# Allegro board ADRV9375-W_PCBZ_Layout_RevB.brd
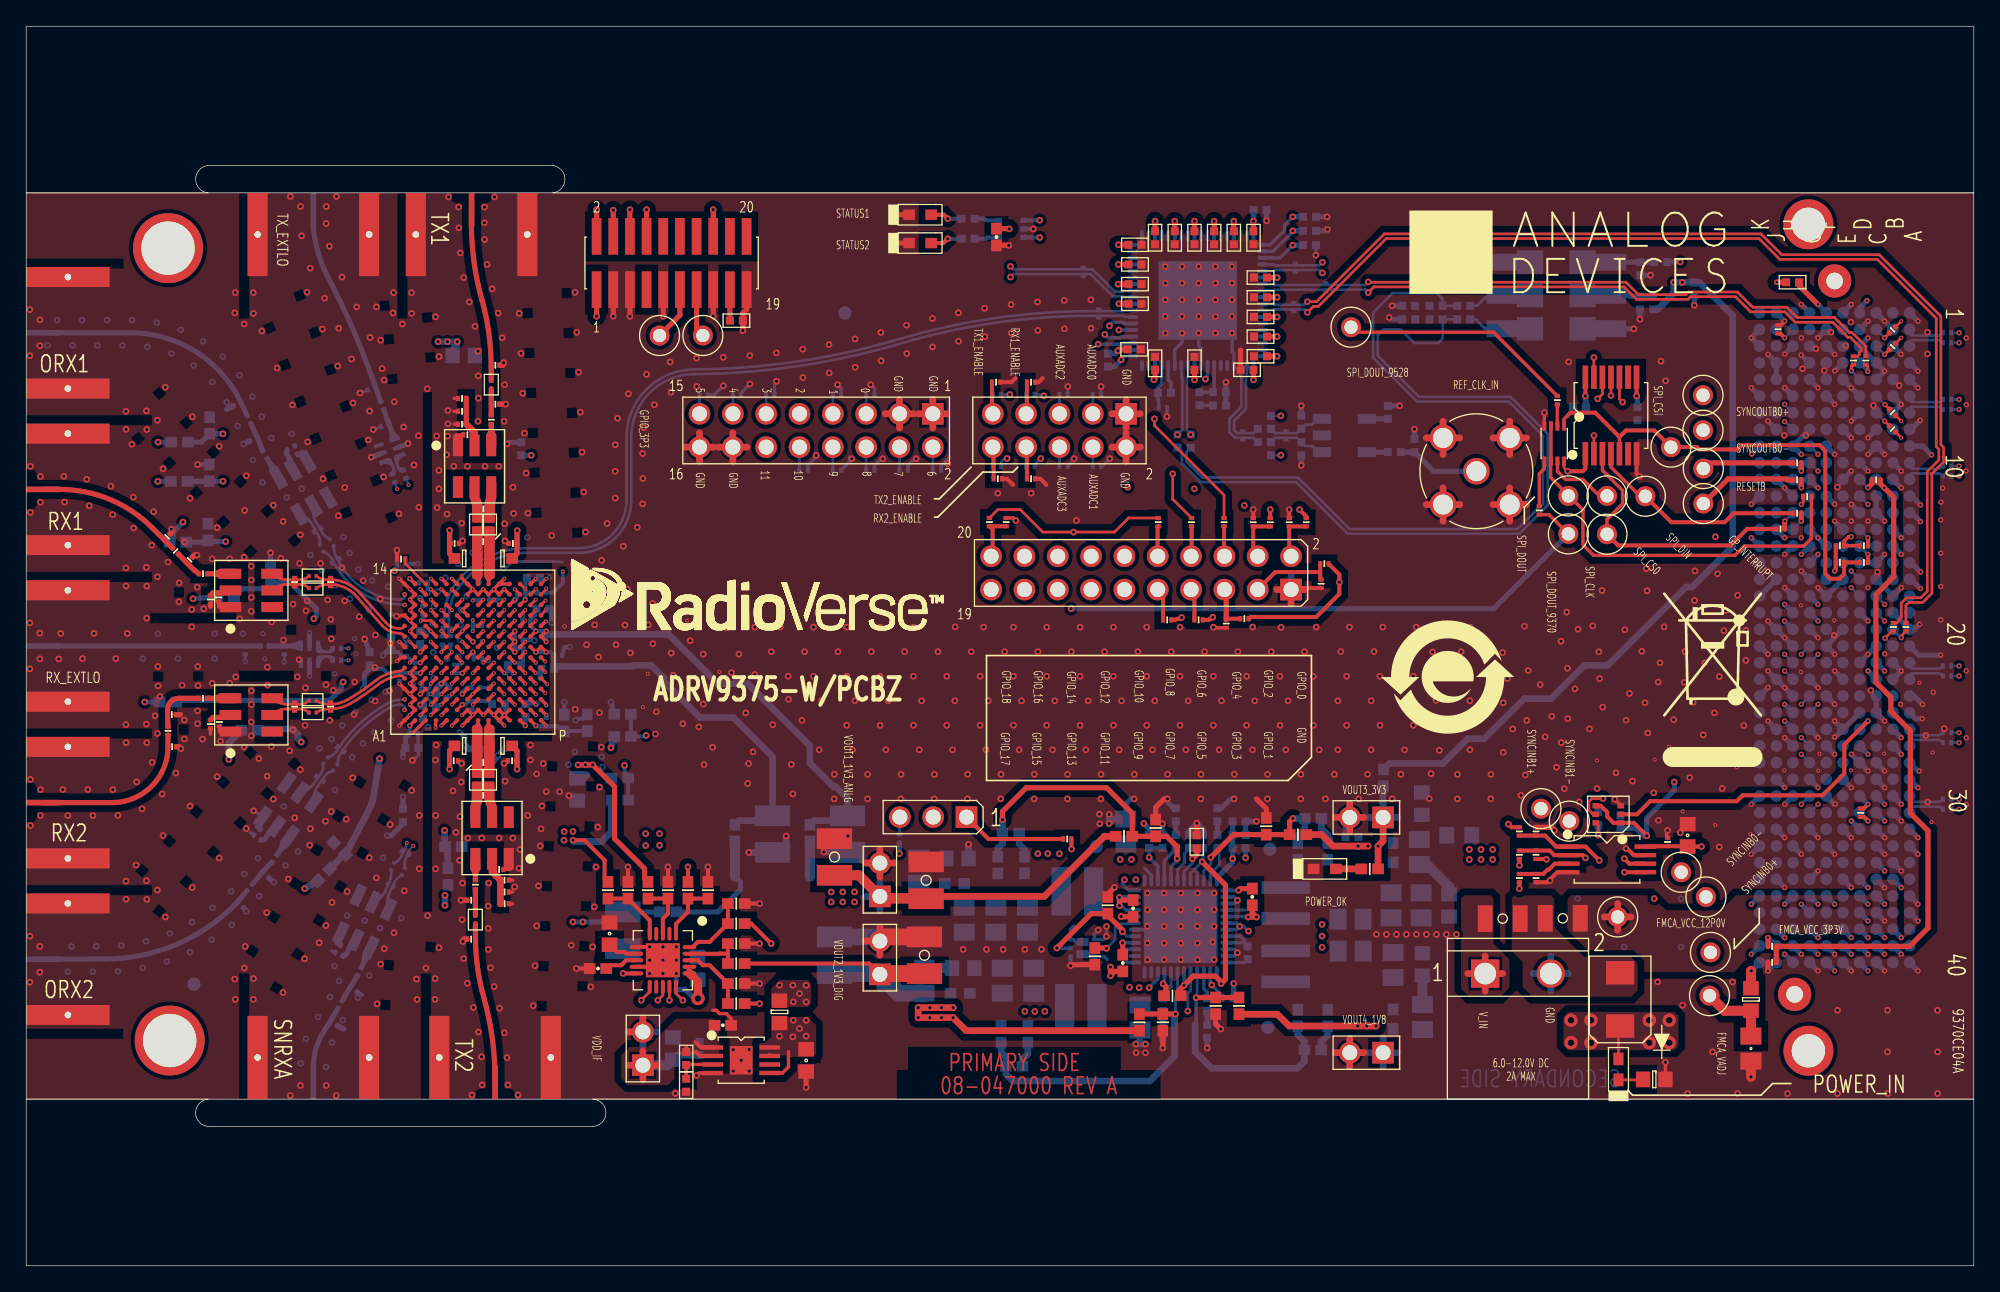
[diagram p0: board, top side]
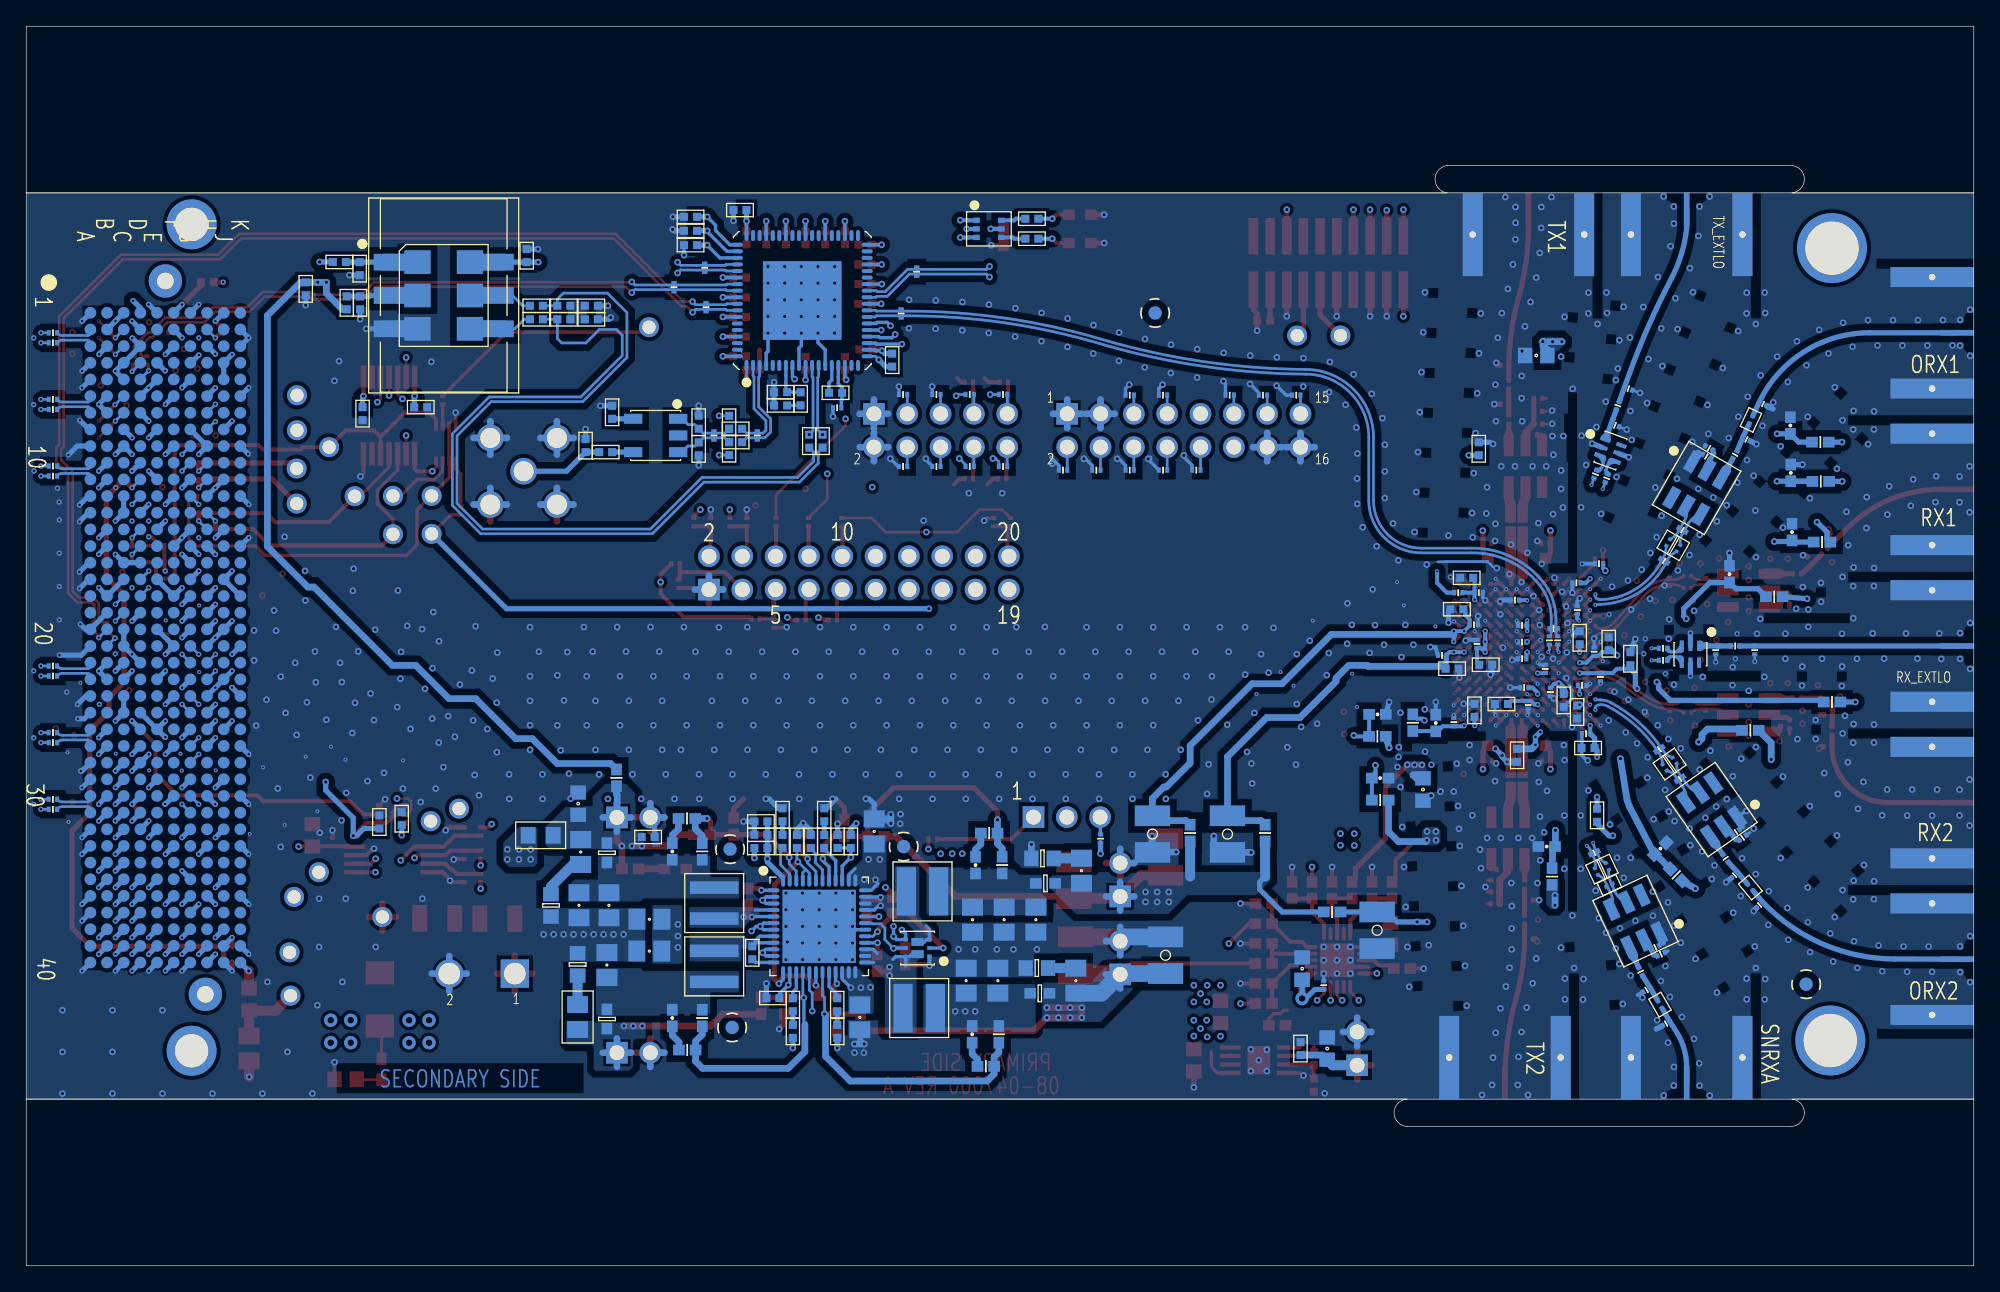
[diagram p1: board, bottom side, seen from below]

Outline 148.44 x 94.49 mm; copper layers: TOP, L2_GND, L3_PWR, L4_GND, L5_SIG, L6_GND, L7_SIG, L8_SIG, L9_GND, L10_SIG, L11_GND, L12_PWR, L13_GND, BOTTOM. Coordinates in mm from the lower left corner of the outline.
Outline path: 0,81.79 0,94.49 148.44,94.49 148.44,81.79 ; 0,81.79 0,12.7 ; 0,81.79 13.85,81.79 arc(12.91,82.83) 13.85,83.87 40.14,83.87 arc(41.06,82.83) 40.14,81.79 148.44,81.79 ; 0,81.79 148.44,81.79 ; 0,12.7 0,0 148.44,0 148.44,12.7 ; 0,12.7 148.44,12.7 ; 0,12.7 13.85,12.7 arc(12.91,11.66) 13.85,10.62 43.19,10.62 arc(44.19,11.66) 43.19,12.7 148.44,12.7 ; 148.44,12.7 148.44,81.79

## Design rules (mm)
net group DIFFPAIR0: nets SERDOUT0+ SERDOUT0-
net group DIFFPAIR1: nets SERDOUT1+ SERDOUT1-
net group DIFFPAIR2: nets SERDOUT3+ SERDOUT3-
net group DIFFPAIR3: nets SERDIN3+ SERDIN3-
net group DIFFPAIR4: nets SERDIN0+ SERDIN0-
net group DIFFPAIR5: nets SERDIN2+ SERDIN2-
net group DIFFPAIR13: nets SERDOUT2+ SERDOUT2-
net group DIFFPAIR15: nets SERDIN1+ SERDIN1-
net group DIFFPAIR16: nets TX_EXTLO+ TX_EXTLO-
net group DIFFPAIR17: nets ORX1+ ORX1-
net group DIFFPAIR18: nets RX1+ RX1-
net group DIFFPAIR19: nets RX2+ RX2-
net group DIFFPAIR20: nets ORX2+ ORX2-
net group DIFFPAIR22: nets RX_EXTLO+ RX_EXTLO-
net group DIFFPAIR24: nets DEV_CLK_IN+ DEV_CLK_IN-
net group DIFFPAIR26: nets GPIO_16 GPIO_17
net group DIFFPAIR27: nets GPIO_13 GPIO_14
net group DIFFPAIR28: nets GPIO_11 GPIO_12
net group DIFFPAIR29: nets GPIO_9 GPIO_10
net group DIFFPAIR30: nets GPIO_8 GPIO_15
net group DIFFPAIR36: nets SYNCOUTB0+ SYNCOUTB0-
net group DIFFPAIR37: nets SYNCINB0+ SYNCINB0-
net group DIFFPAIR38: nets SYNCINB1+ SYNCINB1-
net group DIFFPAIR56: nets SYSREF_IN+ SYSREF_IN-
net group DIFFPAIR59: nets CLK+ CLK-
net group DIFFPAIR61: nets UNNAMED_9_CAP_I337_N1 UNNAMED_9_CAP_I338_N1
net group DIFFPAIR62: nets SNRXA+ SNRXA-
net group DIFFPAIR63: nets FPGA_SYSREF+ FPGA_SYSREF-
net group DIFFPAIR64: nets UNNAMED_6_AD9375_I832_SERDIN2 UNNAMED_6_AD9375_I832_SERDIN2_1
net group DIFFPAIR65: nets UNNAMED_6_AD9375_I832_SERDIN0 UNNAMED_6_AD9375_I832_SERDIN0_1
net group DIFFPAIR66: nets UNNAMED_6_AD9375_I832_SERDIN3 UNNAMED_6_AD9375_I832_SERDIN3_1
net group DIFFPAIR67: nets UNNAMED_6_AD9375_I832_SERDIN1 UNNAMED_6_AD9375_I832_SERDIN1_1
net group DIFFPAIR68: nets UNNAMED_6_AD9375_I832_SERDOUT0 UNNAMED_6_AD9375_I832_SERDOUT0_
net group DIFFPAIR69: nets UNNAMED_6_AD9375_I832_SERDOUT2 UNNAMED_6_AD9375_I832_SERDOUT2_
net group DIFFPAIR70: nets UNNAMED_6_AD9375_I832_SERDOUT1 UNNAMED_6_AD9375_I832_SERDOUT1_
net group DIFFPAIR71: nets UNNAMED_6_AD9375_I832_SERDOUT3 UNNAMED_6_AD9375_I832_SERDOUT3_
net group DIFFPAIR72: nets VCXO_IN+ VCXO_IN-
net group DIFFPAIR73: nets UNNAMED_5_CAP_I916_N1 UNNAMED_5_RES_I897_N2
net group DIFFPAIR74: nets FPGA_REF_CLK+ FPGA_REF_CLK-
net group DIFFPAIR75: nets DIR_CLK+ DIR_CLK-
net group DIFFPAIR76: nets FPGA_AUX_CLK+ FPGA_AUX_CLK-
net group DIFFPAIR77: nets UNNAMED_3_CAP_I109_N1 UNNAMED_3_CAP_I109_N2
net group DIFFPAIR80: nets UNNAMED_3_CAP_I188_N1 UNNAMED_3_CAP_I188_N2
net group DIFFPAIR81: nets UNNAMED_3_CAP_I141_N1 UNNAMED_3_CAP_I141_N2
nets with their own width: min track width 0.254; nets AGND

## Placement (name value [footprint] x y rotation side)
C200  TBD0201  [C0201]  10.74 55.57 45 top
C202  TBD0201  [C0201]  12.45 53.82 45 top
C203  10pF  [C0201]  14.04 50.78 90 top
C204  TBD0201  [C0201]  20.46 52.12 90 top
C207  0.3pF  [C0201]  23.2 52.12 270 top
C208  TBD0201  [C0201]  11.12 39.57 0 top
C211  TBD0201  [C0201]  11.09 42.01 0 top
C212  10pF  [C0201]  14.04 41.29 270 top
C213  TBD0201  [C0201]  20.46 42.62 90 top
C216  0.3pF  [C0201]  23.2 42.62 90 top
C217  0.9PF  [C0201]  23.45 18.46 330 bottom
C219  1PF  [C0201]  24.93 21.03 330 bottom
C220  10pF  [C0201]  23.84 23.75 155 bottom
C224  TBD0201  [C0201]  28.92 31.48 155 bottom
C225  0.2pF  [C0201]  16.07 65.69 205 bottom
C227  TBD0201  [C0201]  17.32 63 205 bottom
C228  10pF  [C0201]  20.17 62.34 30 bottom
C229  0.2pF  [C0201]  22.21 56.09 210 bottom
C232  0.2pF  [C0201]  23.6 53.74 210 bottom
C233  0.2pF  [C0201]  16.31 27.49 320 bottom
C235  TBD0201  [C0201]  18.22 29.77 320 bottom
C236  10pF  [C0201]  17.62 32.63 145 bottom
C237  0.2pF  [C0201]  22.39 37.12 325 bottom
C240  0.2pF  [C0201]  23.97 39.37 325 bottom
C241  220PF  [C0201]  13.47 43.26 0 top
C242  220PF  [C0201]  25.39 22.42 65 bottom
C243  220PF  [C0201]  18.2 61.83 300 bottom
C244  220PF  [C0201]  18.91 31.06 55 bottom
C245  220PF  [C0201]  13.47 52.75 0 top
C246  82PF  [C0201]  14.66 50.95 90 top
C247  82PF  [C0201]  14.72 41.45 90 top
C248  82PF  [C0201]  20.37 61.7 210 bottom
C249  82PF  [C0201]  18.12 33.07 325 bottom
C250  82PF  [C0201]  24.27 24.28 335 bottom
C303  TBD0201  [C0201]  34.85 57.69 0 top
C304  TBD0201  [C0201]  34.83 35.86 180 top
C305  220PF  [C0201]  35.44 64.5 90 top
C306  220PF  [C0201]  34.23 29.05 270 top
C307  0.01uF  [C0201]  32.65 55.06 0 top
C308  0.01uF  [C0201]  37.09 55.06 180 top
C311  0.2pF  [C0201]  34.84 55.19 0 top
C312  3PF  [C0201]  33.22 65.13 0 top
C313  1.4PF  [C0201]  33.22 66.12 0 top
C314  3PF  [C0201]  36.46 28.49 180 top
C315  0.01uF  [C0201]  37.03 38.49 180 top
C316  0.01uF  [C0201]  32.58 38.49 0 top
C319  0.2pF  [C0201]  34.84 38.36 180 top
C320  10uF  [C0603]  33.35 69.39 0 bottom
C321  43PF  [C0201]  33.22 64.15 0 top
C322  1.4PF  [C0201]  36.46 27.59 180 top
C323  0.2pF  [C0201]  35.76 65.68 0 top
C324  0.2pF  [C0201]  35.76 68.65 0 top
C325  10uF  [C0603]  41.98 36.31 270 bottom
C326  43PF  [C0201]  36.46 29.4 180 top
C328  0.2pF  [C0201]  33.92 27.87 180 top
C329  0.2pF  [C0201]  33.92 24.9 180 top
C330  TBD0201  [C0201]  16.69 46.93 270 bottom
C331  TBD0201  [C0201]  19.67 46.93 270 bottom
C332  100pF  [C0201]  23.68 47.07 0 bottom
C333  100pF  [C0201]  23.68 46.15 0 bottom
C334  TBD0201  [C0201]  26.33 66.86 200 bottom
C335  TBD0201  [C0201]  27.34 64.07 200 bottom
C336  100pF  [C0201]  28.84 60.34 290 bottom
C337  100pF  [C0201]  27.98 60.03 290 bottom
C338  51PF  [C0201]  33.63 63.34 0 top
C339  51PF  [C0201]  36.05 30.21 180 top
C401  0.1uF  [C0402#2]  104.28 62.02 180 bottom
C402  0.1uF  [C0402#2]  94.37 63.8 180 bottom
C403  0.1uF  [C0402#2]  94.37 62.79 180 bottom
C404  0.33uF  [C0402#2]  123.02 76.01 270 bottom
C405  0.1uF  [C0402#2]  110.3 77 270 bottom
C406  0.1uF  [C0402#2]  105.37 73.18 0 bottom
C407  0.1uF  [C0402#2]  94.87 62.29 270 bottom
C408  0.1uF  [C0402#2]  88.76 62.86 90 bottom
C409  0.1uF  [C0402#2]  94.87 64.3 90 bottom
C410  180pF  [C0402#2]  90.94 66.59 180 bottom
C411  1uF  [C0402#2]  90.94 65.58 180 bottom
C412  1000pF  [C0402#2]  86.76 66.55 0 bottom
C413  0.47uF  [C0201]  86.63 65.4 0 bottom
C414  0.1uF  [C0402]  73.95 78.42 90 top
C415  0.1uF  [C0402#2]  121.52 33.83 270 bottom
C416  0.1uF  [C0402#2]  119.82 34.08 270 bottom
C417  0.1uF  [C0402#2]  122.81 64.96 90 bottom
C418  0.1uF  [C0402#2]  118.37 65.45 0 bottom
C419  0.1uF  [C0402]  53.1 18.33 180 top
C420  1uF  [C0402#2]  94.04 80.48 0 bottom
C421  0.1uF  [C0402#2]  84.51 77.83 180 top
C422  0.1uF  [C0402#2]  84.51 76.33 180 top
C423  0.1uF  [C0402#2]  84.51 74.83 180 top
C424  0.1uF  [C0402#2]  84.51 73.33 180 top
C425  0.1uF  [C0402#2]  84.45 69.86 180 top
C426  0.1uF  [C0402#2]  86.04 68.79 270 top
C427  0.1uF  [C0402#2]  89.04 68.79 270 top
C428  0.1uF  [C0402#2]  93.04 68.3 0 top
C429  0.1uF  [C0402#2]  94.08 69.33 0 top
C430  0.1uF  [C0402#2]  94.08 70.83 0 top
C431  0.1uF  [C0402#2]  94.08 72.33 0 top
C432  0.1uF  [C0402#2]  94.08 73.83 0 top
C433  0.1uF  [C0402#2]  94.08 75.33 0 top
C434  0.1uF  [C0402#2]  93.54 78.36 90 top
C435  0.1uF  [C0402#2]  92.04 78.36 90 top
C436  0.1uF  [C0402#2]  90.54 78.36 90 top
C437  0.1uF  [C0402#2]  89.04 78.36 90 top
C438  0.1uF  [C0402#2]  87.54 78.36 90 top
C439  0.1uF  [C0402#2]  86.04 78.36 90 top
C501  0.1uF  [C0201]  31.71 47.67 270 bottom
C502  0.1uF  [C0201]  32.34 47.67 270 bottom
C503  0.1uF  [C0201]  79.07 60.93 0 bottom
C504  0.1uF  [C0201]  79.07 66.42 0 bottom
C505  0.1uF  [C0201]  81.61 60.93 0 bottom
C506  0.1uF  [C0201]  81.61 66.42 0 bottom
C507  0.1uF  [C0201]  146.41 39.88 0 bottom
C508  0.1uF  [C0201]  146.41 40.64 0 bottom
C509  0.1uF  [C0201]  142.25 70.07 45 top
C510  0.1uF  [C0201]  142.25 71.34 45 top
C511  0.1uF  [C0201]  146.41 34.8 0 bottom
C512  0.1uF  [C0201]  146.41 35.56 0 bottom
C513  0.1uF  [C0201]  146.41 44.96 0 bottom
C514  0.1uF  [C0201]  146.41 45.72 0 bottom
C515  0.1uF  [C0201]  146.41 70.36 0 bottom
C516  0.1uF  [C0201]  146.41 71.12 0 bottom
C517  0.1uF  [C0201]  146.41 65.28 0 bottom
C518  0.1uF  [C0201]  146.41 66.04 0 bottom
C519  0.1uF  [C0201]  142.25 63.78 315 top
C520  0.1uF  [C0201]  142.25 65.05 315 top
C521  0.1uF  [C0201]  146.41 60.2 0 bottom
C522  0.1uF  [C0201]  146.41 60.96 0 bottom
C523  0.1uF  [C0201]  64.33 66.37 0 bottom
C524  0.1uF  [C0201]  61.79 66.37 0 bottom
C525  0.1uF  [C0201]  56.71 66.37 0 bottom
C526  0.1uF  [C0201]  54.17 66.37 0 bottom
C527  0.1uF  [C0201]  51.63 66.37 0 bottom
C528  0.1uF  [C0201]  69.41 60.65 0 bottom
C529  0.1uF  [C0201]  66.87 60.65 0 bottom
C530  0.1uF  [C0201]  64.33 60.65 0 bottom
C531  0.1uF  [C0201]  61.79 60.65 0 bottom
C532  0.1uF  [C0201]  59.25 60.65 0 bottom
C601  100uF  [C1210]  68.59 29.38 90 top
C602  100uF  [C1210]  61.6 31.16 90 top
C603  1uF  [C0402#2]  29.4 39.47 0 bottom
C604  1uF  [C0402#2]  31.25 43.1 270 bottom
C605  0.1uF  [C0201]  29.55 40.56 0 bottom
C606  0.1uF  [C0201]  32.27 43.73 270 bottom
C608  100uF  [C1210]  45.48 25.57 270 bottom
C609  1uF  [C0402#2]  36 42.82 0 bottom
C610  0.1uF  [C0201]  33.97 42.74 270 bottom
C611  100uF  [C1210]  56.88 32.91 270 bottom
C612  1uF  [C0402#2]  39.76 45.51 180 bottom
C613  0.1uF  [C0201]  40.52 46.53 0 bottom
C614  1uF  [C0402]  32.55 31.96 0 bottom
C615  0.1uF  [C0201]  34.26 44.07 0 bottom
C616  1uF  [C0402]  41 41.37 90 bottom
C617  0.1uF  [C0201]  39.63 41.44 90 bottom
C618  1uF  [C0402]  45.45 42.03 180 bottom
C619  0.1uF  [C0201]  32.66 45.5 90 bottom
C620  1uF  [C0402#2]  26.17 46.27 90 bottom
C621  0.1uF  [C0201]  28.46 44.88 270 bottom
C622  1uF  [C0402]  45.24 37.17 180 bottom
C623  0.1uF  [C0201]  34.43 47.54 0 bottom
C624  1uF  [C0402#2]  27.82 47.42 90 bottom
C625  0.1uF  [C0201]  28.94 46.81 90 bottom
C626  1uF  [C0402]  18.62 52.72 90 bottom
C627  0.1uF  [C0201]  34.43 46.27 0 bottom
C628  1uF  [C0402]  23.89 31.8 135 bottom
C629  0.1uF  [C0201]  29.85 44.24 180 bottom
C630  1uF  [C0402]  13.95 60.44 90 bottom
C631  0.1uF  [C0201]  34.43 48.81 0 bottom
C632  1uF  [C0402]  13.85 55.93 90 bottom
C633  0.1uF  [C0201]  28.56 53.51 0 bottom
C634  1uF  [C0402]  13.98 64.05 90 bottom
C635  0.1uF  [C0201]  34.98 50.75 0 bottom
C636  1uF  [C0402#2]  37.2 45.82 180 bottom
C637  0.1uF  [C0201]  37.86 47.4 90 bottom
C638  100uF  [C1210]  68.46 23.67 90 top
C639  100uF  [C1210]  61.6 23.67 90 bottom
C640  0.1uF  [C0201]  30.22 49.98 90 bottom
C641  0.1uF  [C0201]  30.28 52.05 0 bottom
C642  0.01uF  [C0201]  37.73 51.31 180 bottom
C643  1uF  [C0402#2]  38.65 52.44 0 bottom
C644  1uF  [C0402#2]  38.06 42.34 90 bottom
C645  1uF  [C0402#2]  30.03 47.88 90 bottom
C646  1uF  [C0402#2]  30.24 42.21 270 bottom
C647  1uF  [C0402#2]  37.73 62.28 90 bottom
C648  10uF  [C0603]  51.19 22.65 90 bottom
C649  0.1uF  [C0201]  49.54 21.38 90 bottom
C650  10uF  [C0603]  44.46 25.32 90 top
C651  1uF  [C0402]  43.58 22.66 180 top
C652  100uF  [C1210]  62.6 32.91 270 bottom
C653  1uF  [C0402#2]  39.4 50.05 0 bottom
C654  0.1uF  [C0201]  38.1 48.86 180 bottom
C701  10uF  [C0805H60]  83.81 33.11 90 bottom
C702  1uF  [C0402#2]  89.7 32.35 270 bottom
C703  1uF  [C0402#2]  89.22 32.32 270 top
C704  0.0027uF  [C0402#2]  87.62 34.38 270 bottom
C705  10uF  [C0805H60]  84.9 18.94 270 bottom
C706  0.0027uF  [C0402#2]  86.63 17.87 90 bottom
C707  10uF  [C0805H60]  100.94 26.42 0 bottom
C708  0.0033uF  [C0402#2]  90.79 34.38 270 bottom
C709  10uF  [C0805H60]  100.95 23.99 0 bottom
C710  0.0033uF  [C0402#2]  90 17.87 90 bottom
C711  TBD0402  [C0402#2]  91.53 20.41 180 bottom
C712  TBD0402  [C0402#2]  92.44 33.87 180 bottom
C713  0.1uF  [C0402]  84.37 27.24 90 top
C714  0.01uF  [C0402]  76.09 30.54 270 bottom
C715  0.1uF  [C0402]  83.58 23.08 90 top
C716  0.01uF  [C0402]  76.34 17.64 90 bottom
C717  0.1uF  [C0402]  93.45 28.12 270 top
C718  0.01uF  [C0402]  99.2 31.58 270 bottom
C719  0.1uF  [C0402#2]  93.1 23.86 90 bottom
C720  0.01uF  [C0402]  99.2 18.88 90 bottom
C721  47uF  [C0805H60]  76.31 26.38 270 bottom
C722  47uF  [C0805H60]  73.9 26.38 270 bottom
C723  47uF  [C0805H60]  71.49 26.38 270 bottom
C724  47uF  [C0805H60]  68.01 30.11 90 bottom
C725  47uF  [C0805H60]  76.8 21.73 90 bottom
C726  47uF  [C0805H60]  74.38 21.73 90 bottom
C727  47uF  [C0805H60]  68.44 21.73 90 bottom
C728  47uF  [C0805H60]  104.02 27.48 270 bottom
C729  47uF  [C0805H60]  106.18 31.54 270 bottom
C730  47uF  [C0805H60]  104.18 22.92 90 bottom
C731  22uF  [C0805H53]  106.41 18.96 90 bottom
C732  47uF  [C0805H60]  131.45 16.56 270 top
C733  4.7uF  [C0603]  59.45 15.66 90 top
C734  4.7uF  [C0603]  49.29 16.56 270 bottom
C735  0.01uF  [C0402#2]  51.32 16.56 270 bottom
C736  10uF  [C0603]  106.37 35.23 90 bottom
C737  0.01uF  [C0402#2]  101.04 32.69 0 bottom
C738  0.1uF  [C0402#2]  127.14 74.47 90 bottom
C739  47uF  [C0805H60]  106.31 27.48 270 bottom
C801  0.01uF  [C0201]  143.27 48.69 90 top
C802  0.01uF  [C0201]  142.31 48.69 90 top
C803  0.1uF  [C0201]  125.1 32.3 270 top
C804  10uF  [C0603]  126.63 32.81 90 top
C805  0.01uF  [C0201]  140.22 69.01 270 top
C806  0.01uF  [C0201]  139.26 69.01 270 top
CR701  S2A-TP  [DO214AA3]  121.48 20.3 90 top
D401  SML-E12M8WT86  [LED0603_A]  68.13 77.96 0 top
D402  SML-E12M8WT86  [LED0603_A]  68.13 80.12 0 top
DS701  LNJ926W8CRA  [LED0603]  121.36 14.97 90 top
DS702  SML-E12M8WT86  [LED0603_A]  98.97 30.25 0 top
E601  30OHM  [L0402]  54.01 32.98 90 bottom
E602  30OHM  [L0402]  32.14 29.67 90 bottom
E603  30OHM  [L0402]  42.76 41.4 270 bottom
E604  47OHM AT 100MEGHZ  [L0402]  45.45 40.35 0 bottom
E605  30OHM  [L0402]  17.03 40.81 0 bottom
E606  47OHM AT 100MEGHZ  [L0402]  45.24 35.5 0 bottom
E607  30OHM  [L0402]  10.8 42.97 0 bottom
E608  47OHM AT 100MEGHZ  [L0402]  15.21 51 0 bottom
E609  30OHM  [L0402]  22.68 29.8 45 bottom
E610  30OHM  [L0402]  11.66 59.79 0 bottom
E611  47OHM AT 100MEGHZ  [L0402]  11.57 55.16 0 bottom
E612  30OHM  [L0402]  11.69 62.78 0 bottom
E613  30OHM  [L0402]  59.73 32.98 90 bottom
E701  120OHM  [L0603]  70.75 29.15 180 bottom
E702  470OHM  [L0603]  71.18 20.76 180 bottom
E703  470OHM  [L0603]  104.18 31.48 90 bottom
E704  470OHM  [L0603]  104.18 18.81 270 bottom
E705  42OHM AT 100MEGHZ  [L0805]  109.23 32.81 0 bottom
E706  30OHM  [L0402]  103.45 37.19 90 bottom
F701  2A  [F1206]  117.11 26.48 180 top
F702  2A  [F1206]  112.53 26.46 0 top
J200  132255-11  [CNAMPHENOL132255-11]  0.76 59.18 180 top
J201  132255-11  [CNAMPHENOL132255-11]  0.76 35.31 180 top
J202  132255-11  [CNAMPHENOL132255-11]  21.88 13.46 270 bottom
J203  132255-11  [CNAMPHENOL132255-11]  0.76 71.12 180 bottom
J204  132255-11  [CNAMPHENOL132255-11]  0.76 23.37 180 bottom
J305  132255-11  [CNAMPHENOL132255-11]  33.94 81.03 90 top
J306  132255-11  [CNAMPHENOL132255-11]  35.73 13.46 270 top
J307  132255-11  [CNAMPHENOL132255-11]  0.76 47.24 180 bottom
J308  132255-11  [CNAMPHENOL132255-11]  21.88 81.03 90 bottom
J401  142-0701-201  [CNJOHNSON142-0701-201]  110.53 60.57 0 top
L205  0.6NH  [L0201H13]  21.83 51.66 180 top
L206  0.6NH  [L0201H13]  21.83 52.57 180 top
L214  0.6NH  [L0201H13]  21.83 42.17 180 top
L215  0.6NH  [L0201H13]  21.83 43.08 180 top
L218  1NH  [L0201H13]  23.92 19.91 240 bottom
L221  75NH  [L0201H13]  27.77 29.01 155 bottom
L222  3.3NH  [L0201H13]  28.76 30.05 245 bottom
L223  3.3NH  [L0201H13]  27.93 30.43 245 bottom
L226  0.8NH  [L0201H13]  16.98 64.48 115 bottom
L230  0.7NH  [L0201H13]  23.29 55.13 120 bottom
L231  0.7NH  [L0201H13]  22.51 54.7 120 bottom
L234  0.8NH  [L0201H13]  17.03 28.84 230 bottom
L238  0.7NH  [L0201H13]  22.8 38.51 235 bottom
L239  0.7NH  [L0201H13]  23.55 37.98 235 bottom
L301  0.7NH  [L0201H13]  35.44 67.17 270 top
L302  0.7NH  [L0201H13]  34.23 26.39 90 top
L307  43NH  [L0603]  33.38 53.92 180 top
L308  43NH  [L0603]  36.3 53.92 180 top
L309  0.7NH  [L0201H13]  34.32 56.5 270 top
L310  0.7NH  [L0201H13]  35.3 56.5 270 top
L315  43NH  [L0603]  36.3 39.63 0 top
L316  43NH  [L0603]  33.38 39.63 0 top
L317  0.7NH  [L0201H13]  35.3 37.05 90 top
L318  0.7NH  [L0201H13]  34.32 37.05 90 top
L700  2.2uH  [LSMSQ157H83]  80.12 28.54 180 bottom
L701  2.2uH  [LSMSQ157H83]  80.38 19.65 180 bottom
L702  6.8uH  [LSMSQ157H122]  96 27.65 90 bottom
L703  6.8uH  [LSMSQ157H122]  96 22.82 270 bottom
NOREF  -  []  250.38 231.5 0 top
NOREF#2  -  []  154.73 149.81 0 top
NOREF#3  -  []  65.26 103.22 0 top
NOREF#4  -  [unnamed#2]  135.84 16.39 0 top
NOREF#5  -  [unnamed#2]  10.81 77.57 0 top
NOREF#6  -  []  148.44 12.7 90 top
NOREF#7  -  []  -96.05 -6.87 0 top
NOREF#8  -  []  148.44 12.7 0 top
NOREF#9  -  []  -140.27 -270.64 0 top
NOREF#10  -  []  -140.27 -270.64 0 top
NOREF#11  -  []  0 0 90 top
NOREF#12  -  []  108.34 44.88 0 top
NOREF#13  -  []  -140.27 -270.64 0 top
NOREF#14  -  [unnamed#2]  135.84 79.39 0 top
NOREF#15  -  [unnamed#2]  10.93 17.17 0 top
NOREF#16  -  []  0 81.79 0 top
NOREF#17  -  []  280.93 -28.02 0 top
NOREF#18  -  []  43.34 10.64 0 top
NOREF#19  -  []  100.91 127.05 0 top
NOREF#20  -  []  137.8 54.91 0 top
NOREF#21  -  []  148.44 81.79 0 top
NOREF#22  -  []  0 0 90 top
NOREF#23  -  [unnamed#2]  12.78 21.46 0 bottom
NOREF#24  -  [unnamed#2]  94.79 31.76 0 bottom
NOREF#25  -  [unnamed#2]  94.63 18.17 0 bottom
NOREF#26  -  [unnamed#2]  62.4 72.63 90 bottom
NOREF#27  -  [unnamed#2]  81.56 31.95 0 bottom
NOREF#28  -  []  105.42 74.09 180 bottom
P501  TSW-105-08-G-D  [CNSAMTEC2X5H338LD36]  83.83 64.94 180 top
P502  PEC10DAAN  [CNBERGF2X10H335LD32]  96.4 51.55 180 top
P503  TSW-108-08-G-D  [CNSAMTECTSW-108-08-G-D-ST]  69.1 64.94 180 top
P504  FTSH-110-01-L-DV-K  [CNHDR2X10H251]  49.19 76.44 0 top
P701  Z5.530.3225.0  [CNWIELAND3225]  111.2 22.27 0 top
P702  TSW-103-08-G-S  [CNBERG1X3H205LD36]  71.67 34.2 180 top
P703  TSW-102-08-G-S  [CNSAMTEC1X2H330LD36]  65.06 28.16 90 top
P704  TSW-102-08-G-S  [CNSAMTEC1X2H330LD36]  65.06 22.21 90 top
P705  TSW-102-08-G-S  [CNSAMTEC1X2H330LD36]  103.42 34.18 180 top
P706  TSW-102-08-G-S  [CNSAMTEC1X2H330LD36]  103.42 16.24 180 top
P707  TSW-102-08-G-S  [CNSAMTEC1X2H330LD36]  47 15.29 90 top
P801  ASP-134488-01  [CNSAMTECASP-134488-01]  143.55 72.64 270 bottom
Q701  SIA906EDJ-T1-GE3  [POWERPAKSC70-6]  80.51 24.22 90 bottom
R201  0  [R0201]  11.38 54.48 315 top
R209  0  [R0201]  10.8 40.78 90 top
R312  0  [R0201]  18.18 47.24 0 bottom
R313  0  [R0201]  27.13 65.57 290 bottom
R401  49.9  [R0402#2]  105.81 62.52 270 bottom
R402  0  [R0402#2]  103.78 65.06 270 bottom
R403  24.9  [R0402#2]  97.18 64.3 270 bottom
R404  24.9  [R0402#2]  97.18 62.27 270 bottom
R405  100  [R0201]  96.02 63.29 270 bottom
R406  100  [R0201]  92.72 63.29 270 bottom
R407  0  [R0402#2]  124.57 76.52 180 bottom
R408  0  [R0402#2]  124.01 73.41 270 bottom
R409  0  [R0402#2]  122.99 73.41 90 bottom
R410  0  [R0402#2]  109.56 72.15 180 bottom
R411  0  [R0402#2]  109.56 73.18 180 bottom
R412  49.9  [R0402#2]  107.46 72.15 0 bottom
R413  0  [R0402#2]  107.46 73.18 180 bottom
R414  0  [R0402#2]  87.74 62.86 90 bottom
R415  10.2K  [R0402#2]  89.42 66.09 90 bottom
R416  10K  [R0402#2]  82.44 69.04 270 bottom
R417  10K  [R0402#2]  97.8 77.8 180 bottom
R418  10K  [R0402#2]  97.8 79.96 0 bottom
R419  10K  [R0402#2]  97.8 78.89 0 bottom
R420  200  [R0402#2]  71.79 78.29 180 bottom
R421  200  [R0402#2]  71.79 79.82 180 bottom
R422  100  [R0201]  96.63 73.07 270 bottom
R423  100  [R0201]  96.72 76.08 90 bottom
R424  100  [R0201]  80.57 75.77 270 bottom
R425  100  [R0201]  81.75 72.59 90 bottom
R426  0  [R0201]  116.7 65.99 90 top
R427  0  [R0201]  115.33 57.58 270 top
R428  0  [R0402#2]  105.37 72.15 180 bottom
R429  100  [R0201]  99.07 74.6 270 bottom
R501  100  [R0201]  32.03 48.56 0 bottom
R502  10K  [R0201]  39.29 51.31 0 bottom
R503  10K  [R0201]  133.07 24.35 0 top
R504  1K  [R0201]  133.07 23.13 180 top
R505  14.3K  [R0201]  28.57 53.88 0 top
R506  10K  [R0201]  74.05 59.99 0 top
R507  10K  [R0201]  73.92 67.36 0 top
R508  10K  [R0201]  76.59 67.36 0 top
R509  10K  [R0201]  76.59 59.99 0 top
R510  10K  [R0201]  92.85 49.32 180 top
R511  10K  [R0201]  94.81 56.68 270 top
R512  10K  [R0201]  98.94 53.51 180 top
R513  10K  [R0201]  97.56 56.68 270 top
R514  10K  [R0201]  91.46 48.95 270 top
R515  10K  [R0201]  93.52 56.68 90 top
R516  10K  [R0201]  98.69 51.99 270 top
R517  10K  [R0201]  96.26 56.68 90 top
R518  10K  [R0201]  74.69 56.69 90 top
R519  0  [R0201]  86.97 49.23 0 top
R520  0  [R0201]  86.28 56.69 90 top
R521  0  [R0201]  73.42 56.69 90 top
R522  0  [R0201]  89.35 49.23 0 top
R523  0  [R0201]  88.82 56.69 90 top
R524  0  [R0201]  91.29 56.69 90 top
R525  51K  [R0402#2]  54.13 72.05 180 top
R601  0  [R0402]  48.9 26.97 180 bottom
R602  56K  [R0402]  54.12 19.99 0 top
R603  10K  [R0402]  54.12 21.51 0 top
R604  10K  [R0402]  54.12 23.04 180 top
R605  10K  [R0402]  54.12 24.56 180 top
R606  10K  [R0402]  54.12 26.09 180 top
R607  10K  [R0402]  54.12 27.61 180 top
R608  10K  [R0402]  50.43 28.63 270 top
R609  10K  [R0402]  51.96 28.63 270 top
R610  10K  [R0402]  47.39 28.63 270 top
R611  10K  [R0402]  48.91 28.63 270 top
R612  10K  [R0402]  44.34 28.63 270 top
R613  10K  [R0402]  45.86 28.63 270 top
R614  0  [R0402#2]  34.81 38.91 270 bottom
R615  0  [R0402#2]  28.71 34.34 270 bottom
R701  2K  [R0603]  124.09 14.21 180 top
R702  200  [R0201]  79.35 32.53 180 top
R703  100K  [R0402]  87.36 20.59 0 top
R704  10K  [R0402#2]  87.62 32.35 270 bottom
R705  43.2K  [R0402#2]  85.59 32.35 270 bottom
R706  100K  [R0402#2]  86.6 32.35 90 bottom
R707  10K  [R0402#2]  86.63 19.9 90 bottom
R708  20K  [R0402#2]  90.79 32.35 270 bottom
R709  56K  [R0402#2]  92.44 31.84 180 bottom
R710  14K  [R0402#2]  92.44 32.85 0 bottom
R711  20K  [R0402#2]  90 19.9 90 bottom
R712  0  [R0201]  66.56 32.56 270 bottom
R713  32.4K  [R0402#2]  88.63 32.35 90 bottom
R714  10K  [R0402]  86.08 33.37 90 top
R715  0  [R0402]  75.04 32.98 0 bottom
R716  6.34K  [R0402]  83.67 32.74 180 top
R717  10.7K  [R0402]  74.05 30.54 270 bottom
R718  47K  [R0402]  81.45 23.58 90 top
R719  47K  [R0402]  82.43 27.48 270 top
R720  10K  [R0402]  86.63 18.55 90 top
R721  0  [R0402]  75.3 15.2 0 bottom
R722  10K  [R0402]  74.31 17.64 90 bottom
R723  6.34K  [R0402]  84.85 18.55 270 top
R724  10K  [R0402]  94.51 33.5 270 top
R725  0  [R0402]  98.08 34.1 0 bottom
R726  37.4K  [R0402]  96.91 31.58 270 bottom
R727  31.6K  [R0402]  96.93 32.87 0 top
R728  10K  [R0402]  90.65 19.81 90 top
R729  0  [R0402]  98.06 16.45 0 bottom
R730  27.4K  [R0402]  96.91 18.88 90 bottom
R731  12.7K  [R0402]  92.43 19.81 270 top
R732  0.1  [R0603]  70.98 31.05 0 bottom
R733  0.1  [R0603]  71.41 22.69 0 bottom
R734  0.1  [R0603]  108.45 27.47 270 bottom
R735  200  [R0402]  102.4 30.25 180 top
R736  0  [R0603]  57.41 19.35 270 top
R737  0.47  [R0603]  106.41 22.97 90 bottom
R738  0  [R0603]  131.45 20.3 90 top
R739  20K  [R0402#2]  50.3 15.79 90 top
R740  4.99K  [R0402#2]  50.3 13.76 90 top
R801  0  [R0201]  133.52 71.39 270 top
R802  0  [R0201]  134.98 61.2 0 top
R803  0  [R0201]  134.98 59.91 0 top
R804  0  [R0201]  133.71 56.17 0 top
R805  0  [R0201]  134.98 57.37 0 top
R806  0  [R0201]  135.75 58.64 180 top
R807  1K  [R0402#2]  134.63 74.98 0 top
R808  10K  [R0201]  138.24 54.89 0 top
R809  10K  [R0201]  138.24 53.62 0 top
R810  0  [R0201]  141 59.91 180 top
R811  0  [R0201]  140.06 54.89 0 top
R812  0  [R0201]  140.06 53.62 0 top
R813  0  [R0201]  73.99 66.42 0 bottom
R814  0  [R0201]  76.53 66.42 0 bottom
R815  0  [R0201]  139.81 34.53 90 top
R816  0  [R0201]  73.99 60.93 0 bottom
R817  0  [R0201]  76.53 60.93 0 bottom
R818  20K  [R0201]  113.8 33.11 90 top
R819  20K  [R0201]  115.07 33.11 270 top
R820  20K  [R0201]  113.8 31.33 270 top
R821  20K  [R0201]  115.07 31.33 90 top
R822  20K  [R0201]  113.8 29.55 270 top
R823  20K  [R0201]  115.07 29.55 90 top
T200  TCM1-83X+  [TSML150W160H160]  17.15 51.48 90 top
T201  TCM1-83X+  [TSML150W160H160]  17.15 41.99 90 top
T202  TCM1-83X+  [TSML150W160H160]  25.79 26.27 335 bottom
T203  TCM1-83X+  [TSML150W160H160]  21.12 59.29 210 bottom
T204  TCM1-83X+  [TSML150W160H160]  19.98 34.78 325 bottom
T305  TCM1-83X+  [TSML150W160H160]  34.17 60.94 0 top
T306  TCM1-83X+  [TSML150W160H160]  35.5 32.61 180 top
T307  HHM1595A1  [T0805_A]  21.59 46.61 0 bottom
T308  HHM1595A1  [T0805_A]  27.69 62.15 290 bottom
T401  MABA-007159-000000  [ETC1]  100.47 63.29 270 bottom
TP401  WHT  [CNKEY5001TP]  100.97 71.55 0 top
TP402  WHT  [CNKEY5001TP]  117.54 55.79 0 top
TP501  WHT  [CNKEY5001TP]  51.57 70.91 0 top
TP502  WHT  [CNKEY5001TP]  48.27 70.91 0 top
TP801  WHT  [CNKEY5001TP]  123.41 58.66 0 top
TP802  WHT  [CNKEY5001TP]  120.48 55.77 0 top
TP803  WHT  [CNKEY5001TP]  127.83 58.1 0 top
TP804  WHT  [CNKEY5001TP]  127.83 60.77 0 top
TP805  WHT  [CNKEY5001TP]  127.8 66.36 0 top
TP806  WHT  [CNKEY5001TP]  127.8 63.69 0 top
TP807  WHT  [CNKEY5001TP]  128.03 28.11 45 top
TP808  WHT  [CNKEY5001TP]  126.14 30 45 top
TP809  WHT  [CNKEY5001TP]  117.54 58.69 0 top
TP810  WHT  [CNKEY5001TP]  115.45 34.84 0 top
TP811  WHT  [CNKEY5001TP]  117.61 33.89 0 top
TP812  WHT  [CNKEY5001TP]  128.3 20.59 0 top
TP813  WHT  [CNKEY5001TP]  120.48 58.69 0 top
TP814  WHT  [CNKEY5001TP]  125.36 62.4 0 top
TP815  WHT  [CNKEY5001TP]  121.29 26.59 0 top
TP816  WHT  [CNKEY5001TP]  128.37 23.89 0 top
U101  AD9375BBCZ  [BGA196]  34.04 46.78 0 top
U401  AD9528BCPZ  [QFN72_10X10_PAD5_3X5_3]  89.29 73.58 180 bottom
U402  NC7WZ16P6X  [SC70]  75.07 79.04 270 bottom
U403  NC7WV125K8X  [US8]  116.46 62.68 180 top
U404  ADG3301BKSZ  [SC70-6]  120.58 34.41 90 top
U405  ADG3304SRU-EP  [TSSOP14]  120.79 64.82 0 top
U601  AD7291BCPZ  [QFN20_4X4_PAD2_6X2_6]  48.52 23.29 180 top
U701  ADP5054ACPZ  [QFN48_7X7_PAD5_6X5_6]  88 25.87 270 bottom
U702  ADP125ARHZ-R7  [MSOP8_PAD2_16X1_73]  54.49 15.67 270 top
U801  M24C02-WDW6TP  [TSSOP8]  120.48 30.98 270 top
Y401  122.88MEGHZ  [YSML276W197H71]  116.62 73.96 270 bottom
Y402  122.88MEGHz  [YSML555W358H240]  116.62 73.96 270 bottom
Y403  122.88MEGHZ  [LCC4H210]  116.62 73.96 270 bottom

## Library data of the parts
C200 C202 C204 C208 C211 C213 C224 C227 C235 C303 C304 C330 C331 C334 C335 = CAP: User Part Number: UPN; alternate symbols: (); part number: CAP_SM-TBD0201,TBD0201,TBD0201,E005718,C0201
C203 C212 C220 C228 C236 = CAP: Tolerance: 5; User Part Number: UPN; alternate symbols: (); part number: CAP_SM-10PF,25V,5,E022849,C0201; tolerance: 5
C207 C216 = CAP: Tolerance: 0.1pF; User Part Number: UPN; alternate symbols: (); part number: CAP_SM-0.3PF,25V,0.1PF,E023653,C0201; tolerance: 0.1pF
C217 = CAP: Tolerance: 0.1pF; User Part Number: UPN; alternate symbols: (); part number: CAP_SM-0.9PF,25V,0.1PF,E025900,C0201; tolerance: 0.1pF
C219 = CAP: Tolerance: 0.1pF; User Part Number: UPN; alternate symbols: (); part number: CAP_SM-1PF,25V,0.1PF,E025903,C0201; tolerance: 0.1pF
C225 C229 C232 C233 C237 C240 C311 C319 C323 C324 C328 C329 = CAP: Tolerance: 0.05pF; User Part Number: UPN; alternate symbols: (); part number: CAP_SM-0.2PF,25V,0.05PF,E023663,C0201; tolerance: 0.05pF
C241-C245 C305 C306 = CAP: Tolerance: 5; User Part Number: UPN; alternate symbols: (); part number: CAP_SM-220PF,50V,5,E024874,C0201; tolerance: 5
C246-C250 = CAP: Tolerance: 5; User Part Number: UPN; alternate symbols: (); part number: CAP_SM-82PF,25V,5,E025826,C0201; tolerance: 5
C307 C308 C315 C316 C642 C801 C802 C805 C806 = CAP: Tolerance: 10; User Part Number: UPN; alternate symbols: (); part number: CAP_SM-0.01UF,10V,10,E007201,C0201; tolerance: 10
C312 C314 = CAP: Tolerance: 0.1pF; User Part Number: UPN; alternate symbols: (); part number: CAP_SM-3PF,25V,0.1PF,E025912,C0201; tolerance: 0.1pF
C313 C322 = CAP: Tolerance: 0.1pF; User Part Number: UPN; alternate symbols: (); part number: CAP_SM-1.4PF,25V,0.1PF,E025913,C0201; tolerance: 0.1pF
C320 C325 C648 C650 C736 C804 = CAP: Tolerance: 20; User Part Number: UPN; alternate symbols: (); part number: CAP_SM-10UF,6.3V,20,E007143,C0603; tolerance: 20
C321 C326 = CAP: Tolerance: 2; User Part Number: UPN; alternate symbols: (); part number: CAP_SM-43PF,50V,2,E025911,C0201; tolerance: 2
C332 C333 C336 C337 = CAP: Tolerance: 10; User Part Number: UPN; alternate symbols: (); part number: CAP_SM-100PF,25V,10,E006763,C0201; tolerance: 10
C338 C339 = CAP: Tolerance: 2; User Part Number: UPN; alternate symbols: (); part number: CAP_SM-51PF,50V,2,E025910,C0201; tolerance: 2
C401-C403 C405-C409 C414-C419 C421-C439 C713 C715 C717 C719 C738 = CAP: Tolerance: 10; User Part Number: UPN; alternate symbols: C0402_ALT; part number: CAP_SM-0.1UF,16V,10,E007200,C0402; tolerance: 10
C404 = CAP: Tolerance: 10; User Part Number: UPN; alternate symbols: C0402_ALT; part number: CAP_SM-0.33UF,10V,10,E011273,C0402; tolerance: 10
C410 = CAP: Tolerance: 5; User Part Number: UPN; alternate symbols: C0402_ALT; part number: CAP_SM-180PF,50V,5,E012612,C0402; tolerance: 5
C411 C420 C603 C604 C609 C612 C614 C616 C618 C620 C622 C624 C626 C628 C630 C632 C634 C636 C643-C647 C651 C653 C702 C703 = CAP: Tolerance: 10; User Part Number: UPN; alternate symbols: C0402_ALT; part number: CAP_SM-1UF,6.3V,10,E007449,C0402; tolerance: 10
C412 = CAP: Tolerance: 5; User Part Number: UPN; alternate symbols: C0402_ALT; part number: CAP_SM-1000PF,50V,5,E012419,C0402; tolerance: 5
C413 = CAP: Tolerance: 20; User Part Number: UPN; alternate symbols: (); part number: CAP_SM-0.47UF,4V,20,E008196,C0201; tolerance: 20
C501-C532 C605 C606 C610 C613 C615 C617 C619 C621 C623 C625 C627 C629 C631 C633 C635 C637 C640 C641 C649 C654 C803 = CAP: Tolerance: 10; User Part Number: UPN; alternate symbols: (); part number: CAP_SM-0.1UF,6.3V,10,E011567,C0201; tolerance: 10
C601 C602 C608 C611 C638 C639 C652 = CAP: Tolerance: 20; User Part Number: UPN; alternate symbols: (); part number: CAP_SM-100UF,6.3V,20,E006532,C1210; tolerance: 20
C701 C705 C707 C709 = CAP: Tolerance: 10; User Part Number: UPN; alternate symbols: (); part number: CAP_SM-10UF,25V,10,E014704,C0805H60; tolerance: 10
C704 C706 = CAP: Tolerance: 10; User Part Number: UPN; alternate symbols: C0402_ALT; part number: CAP_SM-0.0027UF,50V,10,E006649,C0402; tolerance: 10
C708 C710 = CAP: Tolerance: 10; User Part Number: UPN; alternate symbols: C0402_ALT; part number: CAP_SM-0.0033UF,50V,10,E007461,C0402; tolerance: 10
C711 C712 = CAP: User Part Number: UPN; alternate symbols: C0402_ALT; part number: CAP_SM-TBD0402,TBD0402,TBD0402,E000381,C0402
C714 C716 C718 C720 C735 C737 = CAP: Tolerance: 10; User Part Number: UPN; alternate symbols: C0402_ALT; part number: CAP_SM-0.01UF,25V,10,E010983,C0402; tolerance: 10
C721-C730 C732 C739 = CAP: Tolerance: 20; User Part Number: UPN; alternate symbols: (); part number: CAP_SM-47UF,6.3V,20,E008247,C0805H60; tolerance: 20
C731 = CAP: Tolerance: 20; User Part Number: UPN; alternate symbols: (); part number: CAP_SM-22UF,6.3V,20,E006534,C0805H53; tolerance: 20
C733 C734 = CAP: Tolerance: 10; User Part Number: UPN; alternate symbols: (); part number: CAP_SM-4.7UF,6.3V,10,E010382,C0603; tolerance: 10
CR701 = DIO: User Part Number: UPN; Tolerance: N/A; alternate symbols: (); part number: DIO_SM-S2A-TP,50V,N/A,E006293,DO214AA3; tolerance: N/A
D401 D402 DS702 = DIOLED: User Part Number: UPN; Tolerance: N/A; alternate symbols: (); part number: DIOLED_SM-SML-E12M8WT86,2.2V,N/A,E024936,LED0603_A; tolerance: N/A
DS701 = DIOLED: Tolerance: N/A; User Part Number: UPN; alternate symbols: (); part number: DIOLED_SM-LNJ926W8CRA,N/A,N/A,E008232,LED0603; tolerance: N/A
E601-E603 E605 E607 E609 E610 E612 E613 E706 = FERRITE: Tolerance: 25; User Part Number: UPN; alternate symbols: (); part number: FERRITE_SM-30OHM,25,E015998,L0402; tolerance: 25
E604 E606 E608 E611 = FERRITE: Tolerance: 25; User Part Number: UPN; alternate symbols: (); part number: FERRITE_SM-47OHM AT 100MEGHZ,25,E021634,L0402; tolerance: 25
E701 = FERRITE: Tolerance: 25; User Part Number: UPN; alternate symbols: (); part number: FERRITE_SM-120OHM,25,E012242,L0603; tolerance: 25
E702-E704 = FERRITE: Tolerance: 25; User Part Number: UPN; alternate symbols: (); part number: FERRITE_SM-470OHM,25,E021228,L0603; tolerance: 25
E705 = FERRITE: Tolerance: 25; User Part Number: UPN; alternate symbols: (); part number: FERRITE_SM-42OHM AT 100MEGHZ,25,E022207,L0805; tolerance: 25
F701 F702 = FSFUSE: Tolerance: N/A; User Part Number: UPN; alternate symbols: (); part number: FSFUSE_SM-2A,63V,E005321,F1206; tolerance: N/A
J200-J204 J305-J308 = CNBNC5P: Tolerance: N/A; User Part Number: UPN; alternate symbols: (CNAMPHENOL132255-11_ALT); part number: CNBNC5P_SM-132255-11,E017863,CNAMPHENOL132255-11; tolerance: N/A
J401 = CNBNC5P: Tolerance: N/A; User Part Number: UPN; alternate symbols: (); part number: CNBNC5P_TH-142-0701-201,E000916,CNJOHNSON142-0701-201; tolerance: N/A
L205 L206 L214 L215 = IND: Tolerance: 0.1NH; User Part Number: UPN; alternate symbols: (); part number: IND_SM-0.6NH,0.1NH,E025890,L0201H13; tolerance: 0.1NH
L218 = IND: Tolerance: 0.1NH; User Part Number: UPN; alternate symbols: (); part number: IND_SM-1NH,0.1NH,E025902,L0201H13; tolerance: 0.1NH
L221 = IND: Tolerance: 3; User Part Number: UPN; alternate symbols: (); part number: IND_SM-75NH,3,E025905,L0201H13; tolerance: 3
L222 L223 = IND: Tolerance: 0.1NH; User Part Number: UPN; alternate symbols: (); part number: IND_SM-3.3NH,0.1NH,E025906,L0201H13; tolerance: 0.1NH
L226 L234 = IND: Tolerance: 0.1NH; User Part Number: UPN; alternate symbols: (); part number: IND_SM-0.8NH,0.1NH,E024882,L0201H13; tolerance: 0.1NH
L230 L231 L238 L239 L301 L302 L309 L310 L317 L318 = IND: Tolerance: 0.1NH; User Part Number: UPN; alternate symbols: (); part number: IND_SM-0.7NH,0.1NH,E025901,L0201H13; tolerance: 0.1NH
L307 L308 L315 L316 = IND: Tolerance: 5; User Part Number: UPN; alternate symbols: (L0603L); part number: IND_SM-43NH,5,E025961,L0603; tolerance: 5
L700 L701 = IND: User Part Number: UPN; Tolerance: 20; alternate symbols: (); part number: IND_SM-2.2UH,20,E016651,LSMSQ157H83; tolerance: 20
L702 L703 = IND: User Part Number: UPN; Tolerance: 20; alternate symbols: (); part number: IND_SM-6.8UH,20,E017909,LSMSQ157H122; tolerance: 20
P501 = CN10P: User Part Number: UPN; Tolerance: N/A; alternate symbols: (); part number: CN10P_TH-TSW-105-08-G-D,E006587,CNSAMTEC2X5H338LD36; tolerance: N/A
P502 = CN20P: Tolerance: N/A; User Part Number: UPN; alternate symbols: (); part number: CN20P_TH-PEC10DAAN,E000765,CNBERGF2X10H335LD32; tolerance: N/A
P503 = CN16P_ODD_EVEN: Tolerance: N/A; User Part Number: UPN; alternate symbols: (); part number: CN16P_ODD_EVEN_TH-TSW-108-08-G-D,E007547,CNSAMTECTSW-108-08-G-D-ST; tolerance: N/A
P504 = CN20P_V2: Tolerance: N/A; User Part Number: UPN; alternate symbols: (); part number: CN20P_V2_SM-FTSH-110-01-L-DV-K,E020976,CNHDR2X10H251; tolerance: N/A
P701 = CN2P: User Part Number: UPN; Tolerance: N/A; alternate symbols: (); part number: CN2P_TH-Z5.530.3225.0,E008161,CNWIELAND3225; tolerance: N/A
P702 = CN3P: User Part Number: UPN; Tolerance: N/A; alternate symbols: (); part number: CN3P_TH-TSW-103-08-G-S,E000812,CNBERG1X3H205LD36; tolerance: N/A
P703-P707 = CN2P: User Part Number: UPN; Tolerance: N/A; alternate symbols: (); part number: CN2P_TH-TSW-102-08-G-S,E006296,CNSAMTEC1X2H330LD36; tolerance: N/A
P801 = CN400P_A_K: User Part Number: UPN; Tolerance: N/A; alternate symbols: (); part number: CN400P_A_K_SM-ASP-134488-01,E011384,CNSAMTECASP-134488-01; tolerance: N/A
Q701 = TRANNMOSFET_2PAD: Tolerance: N/A; User Part Number: UPN; alternate symbols: (); part number: TRANNMOSFET_2PAD_SM-SIA906EDJ-T1-GE3,E015819,POWERPAKSC70-6; tolerance: N/A
R201 R209 R312 R313 R426 R427 R519-R524 R712 R801-R806 R810-R817 = RES: Tolerance: 5; User Part Number: UPN; alternate symbols: (); part number: RES_SM-0,E004015,1/20W,5,R0201; tolerance: 5
R401 R412 = RES: Tolerance: 1; User Part Number: UPN; alternate symbols: R0402_ALT; part number: RES_SM-49.9,E003750,1/16W,1,R0402; tolerance: 1
R402 R407-R411 R413 R414 R428 R601 R614 R615 = RES: Tolerance: 5; User Part Number: UPN; alternate symbols: R0402_ALT; part number: RES_SM-0,E003438,N/A,5,R0402; tolerance: 5
R403 R404 = RES: Tolerance: 1; User Part Number: UPN; alternate symbols: R0402_ALT; part number: RES_SM-24.9,E003773,1/16W,1,R0402; tolerance: 1
R405 R406 = RES: Tolerance: 1; User Part Number: UPN; alternate symbols: R0402_ALT; part number: RES_SM-100,E007239,1/20W,1,R0201; tolerance: 1
R415 = RES: Tolerance: 1; User Part Number: UPN; alternate symbols: R0402_ALT; part number: RES_SM-10.2K,E019451,1/16W,1,R0402; tolerance: 1
R416-R419 R704 R707 = RES: Tolerance: 1; User Part Number: UPN; alternate symbols: R0402_ALT; part number: RES_SM-10K,E003751,1/10W,1,R0402; tolerance: 1
R420 R421 = RES: Tolerance: 1; User Part Number: UPN; alternate symbols: R0402_ALT; part number: RES_SM-200,E003753,1/16W,1,R0402; tolerance: 1
R422-R425 R429 R501 = RES: Tolerance: 1; User Part Number: UPN; alternate symbols: (); part number: RES_SM-100,E007239,1/20W,1,R0201; tolerance: 1
R502 R503 R506-R518 R808 R809 = RES: Tolerance: 1; User Part Number: UPN; alternate symbols: (); part number: RES_SM-10K,E004011,1/20W,1,R0201; tolerance: 1
R504 = RES: Tolerance: 1; User Part Number: UPN; alternate symbols: (); part number: RES_SM-1K,E004010,1/20W,1,R0201; tolerance: 1
R505 = RES: Tolerance: 1; User Part Number: UPN; alternate symbols: (); part number: RES_SM-14.3K,E014068,1/20W,1,R0201; tolerance: 1
R525 = RES: Tolerance: 1; User Part Number: UPN; alternate symbols: R0402_ALT; part number: RES_SM-51K,E013080,1/10W,1,R0402; tolerance: 1
R602 R709 = RES: Tolerance: 1; User Part Number: UPN; alternate symbols: R0402_ALT; part number: RES_SM-56K,E017978,1/10W,1,R0402; tolerance: 1
R603-R613 R714 R720 R722 R724 R728 = RES: Tolerance: 1; User Part Number: UPN; alternate symbols: (R0402L); part number: RES_SM-10K,E003751,1/10W,1,R0402; tolerance: 1
R701 = RES: Tolerance: 1; User Part Number: UPN; alternate symbols: (R0603L); part number: RES_SM-2K,E017866,1/16W,1,R0603; tolerance: 1
R702 = RES: Tolerance: 1; User Part Number: UPN; alternate symbols: (); part number: RES_SM-200,E004008,1/20W,1,R0201; tolerance: 1
R703 R706 = RES: Tolerance: 5; User Part Number: UPN; alternate symbols: R0402_ALT; part number: RES_SM-100K,E003464,1/10W,5,R0402; tolerance: 5
R705 = RES: Tolerance: 1; User Part Number: UPN; alternate symbols: R0402_ALT; part number: RES_SM-43.2K,E018504,1/10W,1,R0402; tolerance: 1
R708 R711 R739 = RES: Tolerance: 1; User Part Number: UPN; alternate symbols: R0402_ALT; part number: RES_SM-20K,E003791,1/16W,1,R0402; tolerance: 1
R710 = RES: Tolerance: 1; User Part Number: UPN; alternate symbols: R0402_ALT; part number: RES_SM-14K,E019660,1/16W,1,R0402; tolerance: 1
R713 = RES: Tolerance: 1; User Part Number: UPN; alternate symbols: R0402_ALT; part number: RES_SM-32.4K,E017609,1/10W,1,R0402; tolerance: 1
R715 R721 R725 R729 = RES: Tolerance: 5; User Part Number: UPN; alternate symbols: (R0402L); part number: RES_SM-0,E003438,N/A,5,R0402; tolerance: 5
R716 R723 = RES: Tolerance: 1; User Part Number: UPN; alternate symbols: (R0402L); part number: RES_SM-6.34K,E003777,1/16W,1,R0402; tolerance: 1
R717 = RES: Tolerance: 1; User Part Number: UPN; alternate symbols: (R0402L); part number: RES_SM-10.7K,E019637,1/16W,1,R0402; tolerance: 1
R718 R719 = RES: Tolerance: 1; User Part Number: UPN; alternate symbols: (R0402L); part number: RES_SM-47K,E008189,1/16W,1,R0402; tolerance: 1
R726 = RES: Tolerance: 1; User Part Number: UPN; alternate symbols: (R0402L); part number: RES_SM-37.4K,E017173,1/10W,1,R0402; tolerance: 1
R727 = RES: Tolerance: 1; User Part Number: UPN; alternate symbols: (R0402L); part number: RES_SM-31.6K,E019881,1/10W,1,R0402; tolerance: 1
R730 = RES: Tolerance: 1; User Part Number: UPN; alternate symbols: (R0402L); part number: RES_SM-27.4K,E021819,1/10W,1,R0402; tolerance: 1
R731 = RES: Tolerance: 1; User Part Number: UPN; alternate symbols: (R0402L); part number: RES_SM-12.7K,E019976,1/10W,1,R0402; tolerance: 1
R732-R734 = RES: Tolerance: 1; User Part Number: UPN; alternate symbols: (R0603L); part number: RES_SM-0.1,E016658,1/10W,1,R0603; tolerance: 1
R735 = RES: Tolerance: 1; User Part Number: UPN; alternate symbols: (R0402L); part number: RES_SM-200,E003753,1/16W,1,R0402; tolerance: 1
R736 R738 = RES: Tolerance: 5; User Part Number: UPN; alternate symbols: (R0603L); part number: RES_SM-0,E006826,1/10W,5,R0603; tolerance: 5
R737 = RES: Tolerance: 5; User Part Number: UPN; alternate symbols: (R0603L); part number: RES_SM-0.47,E015794,1/10W,5,R0603; tolerance: 5
R740 = RES: Tolerance: 1; User Part Number: UPN; alternate symbols: R0402_ALT; part number: RES_SM-4.99K,E006643,1/16W,1,R0402; tolerance: 1
R807 = RES: Tolerance: 5; User Part Number: UPN; alternate symbols: R0402_ALT; part number: RES_SM-1K,E020936,1/16W,5,R0402; tolerance: 5
R818-R823 = RES: Tolerance: 1; User Part Number: UPN; alternate symbols: (); part number: RES_SM-20K,E004013,1/20W,1,R0201; tolerance: 1
T200-T204 T305 T306 = XFMRTCMXXXX_V5: Tolerance: N/A; User Part Number: UPN; alternate symbols: (); part number: XFMRTCMXXXX_V5_SM-TCM1-83X+,E018600,TSML150W160H160; tolerance: N/A
T307 T308 = XFMRBD0826: User Part Number: UPN; Tolerance: N/A; alternate symbols: (); part number: XFMRBD0826_SM-HHM1595A1,E016462,T0805_A; tolerance: N/A
T401 = XFMRETC1: Tolerance: N/A; User Part Number: UPN; alternate symbols: (); part number: XFMRETC1_SM-MABA-007159-000000,E006308,ETC1; tolerance: N/A
TP401 TP402 TP501 TP502 TP801-TP816 = CNTP1P: Tolerance: N/A; User Part Number: UPN; alternate symbols: (); part number: CNTP1P_TH-WHT,E005683,CNKEY5001TP; tolerance: N/A
U101 = AD9375: User Part Number: UPN; Tolerance: N/A; alternate symbols: (); part number: AD9375_SM-AD9375BBCZ,E029410,BGA196; tolerance: N/A
U401 = AD9528: User Part Number: UPN; Tolerance: N/A; alternate symbols: (); part number: AD9528_SM-AD9528BCPZ,E019427,QFN72_10X10_PAD5_3X5_3; tolerance: N/A
U402 = NC7WZ17P6X: Tolerance: N/A; User Part Number: UPN; alternate symbols: (); part number: NC7WZ17P6X_SM-NC7WZ16P6X,E002060,SC70; tolerance: N/A
U403 = CMOSNC7WV125K8X: Tolerance: N/A; User Part Number: UPN; alternate symbols: (); part number: CMOSNC7WV125K8X_SM-NC7WV125K8X,E017378,US8; tolerance: N/A
U404 = ADG3301: Tolerance: N/A; User Part Number: UPN; alternate symbols: (); part number: ADG3301_SM-ADG3301BKSZ,E010847,SC70-6; tolerance: N/A
U405 = ADG3304: Tolerance: N/A; User Part Number: UPN; alternate symbols: (); part number: ADG3304_SM-ADG3304SRU-EP,E020776,TSSOP14; tolerance: N/A
U601 = AD7291: User Part Number: UPN; Tolerance: N/A; alternate symbols: (); part number: AD7291_SM-AD7291BCPZ,E017361,QFN20_4X4_PAD2_6X2_6; tolerance: N/A
U701 = ADP5054: User Part Number: UPN; Tolerance: N/A; alternate symbols: (); part number: ADP5054_SM-ADP5054ACPZ,E019222,QFN48_7X7_PAD5_6X5_6; tolerance: N/A
U702 = ADP125: Tolerance: N/A; User Part Number: UPN; alternate symbols: (); part number: ADP125_SM-ADP125ARHZ-R7,E012587,MSOP8_PAD2_16X1_73; tolerance: N/A
U801 = ICM24CXX: Tolerance: N/A; User Part Number: UPN; alternate symbols: (); part number: ICM24CXX_SM-M24C02-WDW6TP,E017713,TSSOP8; tolerance: N/A
Y401 = XTALOSC6P: Tolerance: N/A; User Part Number: UPN; alternate symbols: (); part number: XTALOSC6P_SM-122.88MEGHZ,E013348,YSML276W197H71; tolerance: N/A
Y402 = XTALOSC6P_V2: Tolerance: N/A; User Part Number: UPN; alternate symbols: (); part number: XTALOSC6P_V2_SM-122.88MEGHZ,E010834,YSML555W358H240; tolerance: N/A
Y403 = XTALCPP: Tolerance: N/A; User Part Number: UPN; alternate symbols: (); part number: XTALCPP_SM-122.88MEGHZ,E015639,LCC4H210; tolerance: N/A

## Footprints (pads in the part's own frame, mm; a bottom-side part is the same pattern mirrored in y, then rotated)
BGA196
  round 0.356 smd: A1(-5.2,-5.2) A2(-5.2,-4.4) A3(-5.2,-3.6) A4(-5.2,-2.8) A5(-5.2,-2) A6(-5.2,-1.2) A7(-5.2,-0.4) A8(-5.2,0.4) A9(-5.2,1.2) A10(-5.2,2) A11(-5.2,2.8) A12(-5.2,3.6) A13(-5.2,4.4) A14(-5.2,5.2) B1(-4.4,-5.2) B2(-4.4,-4.4) B3(-4.4,-3.6) B4(-4.4,-2.8) B5(-4.4,-2) B6(-4.4,-1.2) B7(-4.4,-0.4) B8(-4.4,0.4) B9(-4.4,1.2) B10(-4.4,2) B11(-4.4,2.8) B12(-4.4,3.6) B13(-4.4,4.4) B14(-4.4,5.2) C1(-3.6,-5.2) C2(-3.6,-4.4) C3(-3.6,-3.6) C4(-3.6,-2.8) C5(-3.6,-2) C6(-3.6,-1.2) C7(-3.6,-0.4) C8(-3.6,0.4) C9(-3.6,1.2) C10(-3.6,2) C11(-3.6,2.8) C12(-3.6,3.6) C13(-3.6,4.4) C14(-3.6,5.2) D1(-2.8,-5.2) D2(-2.8,-4.4) D3(-2.8,-3.6) D4(-2.8,-2.8) D5(-2.8,-2) D6(-2.8,-1.2) D7(-2.8,-0.4) D8(-2.8,0.4) D9(-2.8,1.2) D10(-2.8,2) D11(-2.8,2.8) D12(-2.8,3.6) D13(-2.8,4.4) D14(-2.8,5.2) E1(-2,-5.2) E2(-2,-4.4) E3(-2,-3.6) E4(-2,-2.8) E5(-2,-2) E6(-2,-1.2) E7(-2,-0.4) E8(-2,0.4) E9(-2,1.2) E10(-2,2) E11(-2,2.8) E12(-2,3.6) E13(-2,4.4) E14(-2,5.2) F1(-1.2,-5.2) F2(-1.2,-4.4) F3(-1.2,-3.6) F4(-1.2,-2.8) F5(-1.2,-2) F6(-1.2,-1.2) F7(-1.2,-0.4) F8(-1.2,0.4) F9(-1.2,1.2) F10(-1.2,2) F11(-1.2,2.8) F12(-1.2,3.6) F13(-1.2,4.4) F14(-1.2,5.2) G1(-0.4,-5.2) G2(-0.4,-4.4) G3(-0.4,-3.6) G4(-0.4,-2.8) G5(-0.4,-2) G6(-0.4,-1.2) G7(-0.4,-0.4) G8(-0.4,0.4) G9(-0.4,1.2) G10(-0.4,2) G11(-0.4,2.8) G12(-0.4,3.6) G13(-0.4,4.4) G14(-0.4,5.2) H1(0.4,-5.2) H2(0.4,-4.4) H3(0.4,-3.6) H4(0.4,-2.8) H5(0.4,-2) H6(0.4,-1.2) H7(0.4,-0.4) H8(0.4,0.4) H9(0.4,1.2) H10(0.4,2) H11(0.4,2.8) H12(0.4,3.6) H13(0.4,4.4) H14(0.4,5.2) J1(1.2,-5.2) J2(1.2,-4.4) J3(1.2,-3.6) J4(1.2,-2.8) J5(1.2,-2) J6(1.2,-1.2) J7(1.2,-0.4) J8(1.2,0.4) J9(1.2,1.2) J10(1.2,2) J11(1.2,2.8) J12(1.2,3.6) J13(1.2,4.4) J14(1.2,5.2) K1(2,-5.2) K2(2,-4.4) K3(2,-3.6) K4(2,-2.8) K5(2,-2) K6(2,-1.2) K7(2,-0.4) K8(2,0.4) K9(2,1.2) K10(2,2) K11(2,2.8) K12(2,3.6) K13(2,4.4) K14(2,5.2) L1(2.8,-5.2) L2(2.8,-4.4) L3(2.8,-3.6) L4(2.8,-2.8) L5(2.8,-2) L6(2.8,-1.2) L7(2.8,-0.4) L8(2.8,0.4) L9(2.8,1.2) L10(2.8,2) L11(2.8,2.8) L12(2.8,3.6) L13(2.8,4.4) L14(2.8,5.2) M1(3.6,-5.2) M2(3.6,-4.4) M3(3.6,-3.6) M4(3.6,-2.8) M5(3.6,-2) M6(3.6,-1.2) M7(3.6,-0.4) M8(3.6,0.4) M9(3.6,1.2) M10(3.6,2) M11(3.6,2.8) M12(3.6,3.6) M13(3.6,4.4) M14(3.6,5.2) N1(4.4,-5.2) N2(4.4,-4.4) N3(4.4,-3.6) N4(4.4,-2.8) N5(4.4,-2) N6(4.4,-1.2) N7(4.4,-0.4) N8(4.4,0.4) N9(4.4,1.2) N10(4.4,2) N11(4.4,2.8) N12(4.4,3.6) N13(4.4,4.4) N14(4.4,5.2) P1(5.2,-5.2) P2(5.2,-4.4) P3(5.2,-3.6) P4(5.2,-2.8) P5(5.2,-2) P6(5.2,-1.2) P7(5.2,-0.4) P8(5.2,0.4) P9(5.2,1.2) P10(5.2,2) P11(5.2,2.8) P12(5.2,3.6) P13(5.2,4.4) P14(5.2,5.2)
C0201
  rect 0.305x0.406 smd: 1(-0.318,0) 2(0.318,0)
C0402
  rect 0.889x0.813 smd: 1(-0.635,0) 2(0.635,0)
C0402#2
  rect 0.61x0.61 smd: 1(-0.495,0) 2(0.495,0)
C0603
  rect 1.092x1.194 smd: 1(-0.851,0) 2(0.851,0)
C0805H53
  rect 1.295x1.6 smd: 1(-0.953,0) 2(0.953,0)
C0805H60
  rect 1.295x1.6 smd: 1(-0.953,0) 2(0.953,0)
C1210
  rect 1.575x2.692 smd: 1(-1.397,0) 2(1.397,0)
CNAMPHENOL132255-11
  rect 2.54x0.432 smd: 1(-0.508,0)
  rect 6.35x1.524 hole 0.508: 2(-2.413,4.25) 4(-2.413,-4.25)
  round 0.305 smd: 3(-2.413,4.25) 5(-2.413,-4.25)
CNBERG1X3H205LD36
  rect 1.651x1.651 hole 1.143: 1(0,0)
  round 1.651 hole 1.143: 2(2.54,0) 3(5.08,0)
CNBERGF2X10H335LD32
  rect 1.651x1.651 hole 1.143: 1(0,0)
  round 1.651 hole 1.143: 2(0,-2.54) 3(2.54,0) 4(2.54,-2.54) 5(5.08,0) 6(5.08,-2.54) 7(7.62,0) 8(7.62,-2.54) 9(10.16,0) 10(10.16,-2.54) 11(12.7,0) 12(12.7,-2.54) 13(15.24,0) 14(15.24,-2.54) 15(17.78,0) 16(17.78,-2.54) 17(20.32,0) 18(20.32,-2.54) 19(22.86,0) 20(22.86,-2.54)
CNHDR2X10H251
  rect 0.737x2.794 smd: 1(-5.715,-2.032) 2(-5.715,2.032) 3(-4.445,-2.032) 4(-4.445,2.032) 5(-3.175,-2.032) 6(-3.175,2.032) 7(-1.905,-2.032) 8(-1.905,2.032) 9(-0.635,-2.032) 10(-0.635,2.032) 11(0.635,-2.032) 12(0.635,2.032) 13(1.905,-2.032) 14(1.905,2.032) 15(3.175,-2.032) 16(3.175,2.032) 17(4.445,-2.032) 18(4.445,2.032) 19(5.715,-2.032) 20(5.715,2.032)
CNJOHNSON142-0701-201
  round 2.032 hole 1.524: 1(0,0) 2(-2.54,2.54) 3(2.54,2.54) 4(2.54,-2.54) 5(-2.54,-2.54)
CNKEY5001TP
  round 1.524 hole 1.016: 1(0,0)
CNSAMTEC1X2H330LD36
  rect 1.651x1.651 hole 1.143: 1(0,0)
  round 1.651 hole 1.143: 2(2.54,0)
CNSAMTEC2X5H338LD36
  rect 1.651x1.651 hole 1.143: 1(0,0)
  round 1.651 hole 1.143: 2(0,2.54) 3(2.54,0) 4(2.54,2.54) 5(5.08,0) 6(5.08,2.54) 7(7.62,0) 8(7.62,2.54) 9(10.16,0) 10(10.16,2.54)
CNSAMTECASP-134488-01
  round 2.54 hole 1.27 unplated: (-2.426,5.715) (51.956,8.763)
  round 0.889 smd: A1(0,0) A2(1.27,0) A3(2.54,0) A4(3.81,0) A5(5.08,0) A6(6.35,0) A7(7.62,0) A8(8.89,0) A9(10.16,0) A10(11.43,0) A11(12.7,0) A12(13.97,0) A13(15.24,0) A14(16.51,0) A15(17.78,0) A16(19.05,0) A17(20.32,0) A18(21.59,0) A19(22.86,0) A20(24.13,0) A21(25.4,0) A22(26.67,0) A23(27.94,0) A24(29.21,0) A25(30.48,0) A26(31.75,0) A27(33.02,0) A28(34.29,0) A29(35.56,0) A30(36.83,0) A31(38.1,0) A32(39.37,0) A33(40.64,0) A34(41.91,0) A35(43.18,0) A36(44.45,0) A37(45.72,0) A38(46.99,0) A39(48.26,0) A40(49.53,0) B1(0,1.27) B2(1.27,1.27) B3(2.54,1.27) B4(3.81,1.27) B5(5.08,1.27) B6(6.35,1.27) B7(7.62,1.27) B8(8.89,1.27) B9(10.16,1.27) B10(11.43,1.27) B11(12.7,1.27) B12(13.97,1.27) B13(15.24,1.27) B14(16.51,1.27) B15(17.78,1.27) B16(19.05,1.27) B17(20.32,1.27) B18(21.59,1.27) B19(22.86,1.27) B20(24.13,1.27) B21(25.4,1.27) B22(26.67,1.27) B23(27.94,1.27) B24(29.21,1.27) B25(30.48,1.27) B26(31.75,1.27) B27(33.02,1.27) B28(34.29,1.27) B29(35.56,1.27) B30(36.83,1.27) B31(38.1,1.27) B32(39.37,1.27) B33(40.64,1.27) B34(41.91,1.27) B35(43.18,1.27) B36(44.45,1.27) B37(45.72,1.27) B38(46.99,1.27) B39(48.26,1.27) B40(49.53,1.27) C1(0,2.54) C2(1.27,2.54) C3(2.54,2.54) C4(3.81,2.54) C5(5.08,2.54) C6(6.35,2.54) C7(7.62,2.54) C8(8.89,2.54) C9(10.16,2.54) C10(11.43,2.54) C11(12.7,2.54) C12(13.97,2.54) C13(15.24,2.54) C14(16.51,2.54) C15(17.78,2.54) C16(19.05,2.54) C17(20.32,2.54) C18(21.59,2.54) C19(22.86,2.54) C20(24.13,2.54) C21(25.4,2.54) C22(26.67,2.54) C23(27.94,2.54) C24(29.21,2.54) C25(30.48,2.54) C26(31.75,2.54) C27(33.02,2.54) C28(34.29,2.54) C29(35.56,2.54) C30(36.83,2.54) C31(38.1,2.54) C32(39.37,2.54) C33(40.64,2.54) C34(41.91,2.54) C35(43.18,2.54) C36(44.45,2.54) C37(45.72,2.54) C38(46.99,2.54) C39(48.26,2.54) C40(49.53,2.54) D1(0,3.81) D2(1.27,3.81) D3(2.54,3.81) D4(3.81,3.81) D5(5.08,3.81) D6(6.35,3.81) D7(7.62,3.81) D8(8.89,3.81) D9(10.16,3.81) D10(11.43,3.81) D11(12.7,3.81) D12(13.97,3.81) D13(15.24,3.81) D14(16.51,3.81) D15(17.78,3.81) D16(19.05,3.81) D17(20.32,3.81) D18(21.59,3.81) D19(22.86,3.81) D20(24.13,3.81) D21(25.4,3.81) D22(26.67,3.81) D23(27.94,3.81) D24(29.21,3.81) D25(30.48,3.81) D26(31.75,3.81) D27(33.02,3.81) D28(34.29,3.81) D29(35.56,3.81) D30(36.83,3.81) D31(38.1,3.81) D32(39.37,3.81) D33(40.64,3.81) D34(41.91,3.81) D35(43.18,3.81) D36(44.45,3.81) D37(45.72,3.81) D38(46.99,3.81) D39(48.26,3.81) D40(49.53,3.81) E1(0,5.08) E2(1.27,5.08) E3(2.54,5.08) E4(3.81,5.08) E5(5.08,5.08) E6(6.35,5.08) E7(7.62,5.08) E8(8.89,5.08) E9(10.16,5.08) E10(11.43,5.08) E11(12.7,5.08) E12(13.97,5.08) E13(15.24,5.08) E14(16.51,5.08) E15(17.78,5.08) E16(19.05,5.08) E17(20.32,5.08) E18(21.59,5.08) E19(22.86,5.08) E20(24.13,5.08) E21(25.4,5.08) E22(26.67,5.08) E23(27.94,5.08) E24(29.21,5.08) E25(30.48,5.08) E26(31.75,5.08) E27(33.02,5.08) E28(34.29,5.08) E29(35.56,5.08) E30(36.83,5.08) E31(38.1,5.08) E32(39.37,5.08) E33(40.64,5.08) E34(41.91,5.08) E35(43.18,5.08) E36(44.45,5.08) E37(45.72,5.08) E38(46.99,5.08) E39(48.26,5.08) E40(49.53,5.08) F1(0,6.35) F2(1.27,6.35) F3(2.54,6.35) F4(3.81,6.35) F5(5.08,6.35) F6(6.35,6.35) F7(7.62,6.35) F8(8.89,6.35) F9(10.16,6.35) F10(11.43,6.35) F11(12.7,6.35) F12(13.97,6.35) F13(15.24,6.35) F14(16.51,6.35) F15(17.78,6.35) F16(19.05,6.35) F17(20.32,6.35) F18(21.59,6.35) F19(22.86,6.35) F20(24.13,6.35) F21(25.4,6.35) F22(26.67,6.35) F23(27.94,6.35) F24(29.21,6.35) F25(30.48,6.35) F26(31.75,6.35) F27(33.02,6.35) F28(34.29,6.35) F29(35.56,6.35) F30(36.83,6.35) F31(38.1,6.35) F32(39.37,6.35) F33(40.64,6.35) F34(41.91,6.35) F35(43.18,6.35) F36(44.45,6.35) F37(45.72,6.35) F38(46.99,6.35) F39(48.26,6.35) F40(49.53,6.35) G1(0,7.62) G2(1.27,7.62) G3(2.54,7.62) G4(3.81,7.62) G5(5.08,7.62) G6(6.35,7.62) G7(7.62,7.62) G8(8.89,7.62) G9(10.16,7.62) G10(11.43,7.62) G11(12.7,7.62) G12(13.97,7.62) G13(15.24,7.62) G14(16.51,7.62) G15(17.78,7.62) G16(19.05,7.62) G17(20.32,7.62) G18(21.59,7.62) G19(22.86,7.62) G20(24.13,7.62) G21(25.4,7.62) G22(26.67,7.62) G23(27.94,7.62) G24(29.21,7.62) G25(30.48,7.62) G26(31.75,7.62) G27(33.02,7.62) G28(34.29,7.62) G29(35.56,7.62) G30(36.83,7.62) G31(38.1,7.62) G32(39.37,7.62) G33(40.64,7.62) G34(41.91,7.62) G35(43.18,7.62) G36(44.45,7.62) G37(45.72,7.62) G38(46.99,7.62) G39(48.26,7.62) G40(49.53,7.62) H1(0,8.89) H2(1.27,8.89) H3(2.54,8.89) H4(3.81,8.89) H5(5.08,8.89) H6(6.35,8.89) H7(7.62,8.89) H8(8.89,8.89) H9(10.16,8.89) H10(11.43,8.89) H11(12.7,8.89) H12(13.97,8.89) H13(15.24,8.89) H14(16.51,8.89) H15(17.78,8.89) H16(19.05,8.89) H17(20.32,8.89) H18(21.59,8.89) H19(22.86,8.89) H20(24.13,8.89) H21(25.4,8.89) H22(26.67,8.89) H23(27.94,8.89) H24(29.21,8.89) H25(30.48,8.89) H26(31.75,8.89) H27(33.02,8.89) H28(34.29,8.89) H29(35.56,8.89) H30(36.83,8.89) H31(38.1,8.89) H32(39.37,8.89) H33(40.64,8.89) H34(41.91,8.89) H35(43.18,8.89) H36(44.45,8.89) H37(45.72,8.89) H38(46.99,8.89) H39(48.26,8.89) H40(49.53,8.89) J1(0,10.16) J2(1.27,10.16) J3(2.54,10.16) J4(3.81,10.16) J5(5.08,10.16) J6(6.35,10.16) J7(7.62,10.16) J8(8.89,10.16) J9(10.16,10.16) J10(11.43,10.16) J11(12.7,10.16) J12(13.97,10.16) J13(15.24,10.16) J14(16.51,10.16) J15(17.78,10.16) J16(19.05,10.16) J17(20.32,10.16) J18(21.59,10.16) J19(22.86,10.16) J20(24.13,10.16) J21(25.4,10.16) J22(26.67,10.16) J23(27.94,10.16) J24(29.21,10.16) J25(30.48,10.16) J26(31.75,10.16) J27(33.02,10.16) J28(34.29,10.16) J29(35.56,10.16) J30(36.83,10.16) J31(38.1,10.16) J32(39.37,10.16) J33(40.64,10.16) J34(41.91,10.16) J35(43.18,10.16) J36(44.45,10.16) J37(45.72,10.16) J38(46.99,10.16) J39(48.26,10.16) J40(49.53,10.16) K1(0,11.43) K2(1.27,11.43) K3(2.54,11.43) K4(3.81,11.43) K5(5.08,11.43) K6(6.35,11.43) K7(7.62,11.43) K8(8.89,11.43) K9(10.16,11.43) K10(11.43,11.43) K11(12.7,11.43) K12(13.97,11.43) K13(15.24,11.43) K14(16.51,11.43) K15(17.78,11.43) K16(19.05,11.43) K17(20.32,11.43) K18(21.59,11.43) K19(22.86,11.43) K20(24.13,11.43) K21(25.4,11.43) K22(26.67,11.43) K23(27.94,11.43) K24(29.21,11.43) K25(30.48,11.43) K26(31.75,11.43) K27(33.02,11.43) K28(34.29,11.43) K29(35.56,11.43) K30(36.83,11.43) K31(38.1,11.43) K32(39.37,11.43) K33(40.64,11.43) K34(41.91,11.43) K35(43.18,11.43) K36(44.45,11.43) K37(45.72,11.43) K38(46.99,11.43) K39(48.26,11.43) K40(49.53,11.43)
